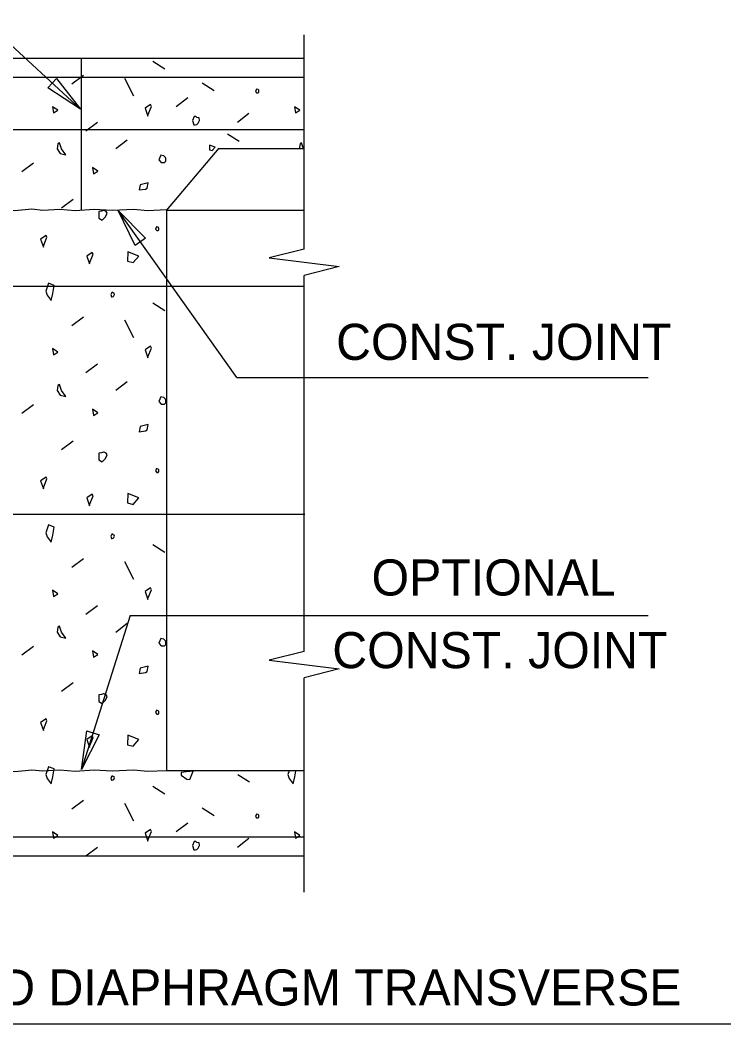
# Model space of a CAD drawing. Extents: x 0 to 34, y 0 to 23.5.
# Drawn here: x 21.208 to 24.17, y 15.614 to 19.798 of the extents above; entities that cross this region are included whole.
import ezdxf

# ---------------------------------------------------------------- set-up
doc = ezdxf.new("R2010")
doc.units = 0
for name, color, linetype in [('BRDG_ANNO_General-Notes', 7, 'Continuous'), ('BRDG_BASE_Obj-Line', 7, 'Continuous'), ('BRDG_BASE_Pattern', 7, 'Continuous'), ('BRDG_BASE_Rebar', 7, 'Continuous')]:
    doc.layers.add(name, color=color, linetype=linetype)

msp = doc.modelspace()

# ---------------------------------------------------------------- linework, layer by layer
at = {"layer": 'BRDG_ANNO_General-Notes'}
for p, q in [((20.8763, 19.966), (21.4595, 19.4264)), ((21.324, 19.5155), (21.3602, 19.5546)), ((21.3602, 19.5546), (21.4595, 19.4264)), ((21.4595, 19.4264), (21.324, 19.5155)), ((22.1111, 18.3085), (21.6165, 19.0045)), ((21.6874, 18.8586), (21.6165, 19.0045)), ((21.6165, 19.0045), (21.7309, 18.8896)), ((21.7309, 18.8896), (21.6874, 18.8586)), ((22.1111, 18.3085), (23.8259, 18.3085)), ((21.6666, 17.3169), (21.4636, 16.6744)), ((21.6666, 17.3169), (23.8259, 17.3169)), ((21.4636, 16.6744), (21.4864, 16.835)), ((21.4864, 16.835), (21.5372, 16.8189)), ((21.5372, 16.8189), (21.4636, 16.6744)), ((20.1671, 15.6141), (24.1701, 15.6141))]:
    msp.add_line(p, q, dxfattribs=at)
at = {"layer": 'BRDG_BASE_Obj-Line'}
for p, q in [((22.3924, 18.8436), (22.3924, 19.7368)), ((22.3924, 19.6379), (18.0383, 19.6379)), ((21.4622, 19.6379), (21.4622, 19.0045)), ((21.8185, 19.0045), (22.0383, 19.2644)), ((22.3924, 19.2618), (22.0362, 19.2618)), ((22.3924, 19.0045), (21.8185, 19.0045)), ((21.8185, 19.0045), (21.8185, 16.6691)), ((22.3924, 18.8436), (22.2466, 18.8071)), ((22.2466, 18.8071), (22.5383, 18.7707)), ((22.5383, 18.7707), (22.3924, 18.7342)), ((22.3924, 17.1665), (22.3924, 18.7342)), ((22.3924, 17.1665), (22.2466, 17.1301)), ((22.2466, 17.1301), (22.5383, 17.0936)), ((22.5383, 17.0936), (22.3924, 17.0571)), ((22.3924, 16.1639), (22.3924, 17.0571)), ((22.3924, 16.6691), (21.8185, 16.6691)), ((22.3924, 16.3129), (18.0383, 16.3129))]:
    msp.add_line(p, q, dxfattribs=at)
for points in [[(21.8185, 19.0067), (21.7392, 19.0034), (21.6823, 19.0088), (21.5921, 19.0046), (21.5175, 19.0091), (21.4371, 19.0036), (21.3743, 19.0093), (21.3036, 19.0046), (21.2566, 19.01), (21.1859, 19.0029), (21.1369, 19.0093), (21.106, 19.0067)], [(21.8185, 16.6691), (21.7392, 16.6658), (21.6823, 16.6713), (21.5921, 16.6671), (21.5175, 16.6715), (21.4371, 16.6661), (21.3743, 16.6717), (21.3036, 16.6671), (21.2566, 16.6724), (21.1859, 16.6654), (21.1369, 16.6717), (21.106, 16.6691)]]:
    msp.add_lwpolyline(points, dxfattribs=at)
at = {"layer": 'BRDG_BASE_Pattern'}
for p, q in [((21.7613, 19.6269), (21.8107, 19.5956)), ((21.4722, 19.5672), (21.4241, 19.5306)), ((21.6438, 19.5561), (21.6804, 19.4826)), ((21.9676, 19.5366), (22.0171, 19.5053)), ((21.9071, 19.4734), (21.859, 19.4368)), ((22.1618, 19.4084), (22.1136, 19.3718)), ((21.5305, 19.3715), (21.4824, 19.3349)), ((21.6548, 19.2976), (21.6067, 19.2609)), ((22.0718, 19.3245), (22.1213, 19.2932)), ((21.2637, 19.202), (21.2156, 19.1654)), ((21.4288, 19.0508), (21.3806, 19.0142)), ((21.8355, 19.0312), (21.8391, 19.0289)), ((21.7613, 18.6195), (21.8107, 18.5883)), ((21.4722, 18.5598), (21.4241, 18.5232)), ((21.6438, 18.5487), (21.6804, 18.4752)), ((21.5305, 18.3642), (21.4824, 18.3276)), ((21.6548, 18.2902), (21.6067, 18.2536)), ((21.2637, 18.1946), (21.2156, 18.158)), ((21.4288, 18.0435), (21.3806, 18.0069)), ((21.7613, 17.6122), (21.8107, 17.5809)), ((21.4722, 17.5525), (21.4241, 17.5159)), ((21.6438, 17.5414), (21.6804, 17.4679)), ((21.5305, 17.3568), (21.4824, 17.3202)), ((21.6548, 17.2829), (21.6067, 17.2462)), ((21.2637, 17.1873), (21.2156, 17.1507)), ((21.4288, 17.0361), (21.3806, 16.9995)), ((22.1149, 16.6539), (22.1644, 16.6226)), ((21.7613, 16.6048), (21.8107, 16.5736)), ((21.4722, 16.5452), (21.4241, 16.5085)), ((21.6438, 16.5341), (21.6804, 16.4605)), ((21.9676, 16.5145), (22.0171, 16.4833)), ((21.9071, 16.4514), (21.859, 16.4148)), ((22.1618, 16.3864), (22.1136, 16.3498)), ((21.5305, 16.3495), (21.4824, 16.3129))]:
    msp.add_line(p, q, dxfattribs=at)
for points in [[(22.1932, 19.5105), (22.1886, 19.5003), (22.194, 19.4947), (22.2006, 19.4947), (22.2033, 19.4977), (22.2033, 19.5031), (22.2024, 19.5057), (22.1996, 19.5087)], [(21.3438, 19.4367), (21.3474, 19.4109), (21.3659, 19.422)], [(21.7298, 19.4313), (21.7412, 19.3981), (21.7412, 19.4017), (21.7559, 19.4386), (21.7521, 19.446)], [(22.3521, 19.4367), (22.3558, 19.4109), (22.3743, 19.422)], [(21.9264, 19.3796), (21.9322, 19.3611), (21.9376, 19.3611), (21.9451, 19.363), (21.9505, 19.3683), (21.9558, 19.3796), (21.9543, 19.3905), (21.9451, 19.3924), (21.9411, 19.3962), (21.9338, 19.3962)], [(21.3662, 19.2826), (21.3621, 19.2619), (21.3759, 19.2416), (21.3989, 19.237), (21.3805, 19.2614), (21.3727, 19.2867)], [(21.9981, 19.2771), (21.9972, 19.2573), (22.0092, 19.2546), (22.0207, 19.2679)], [(21.7952, 19.2355), (21.7859, 19.2153), (21.7967, 19.2041), (21.8099, 19.2041), (21.8154, 19.2099), (21.8154, 19.2207), (21.8135, 19.226), (21.8078, 19.232)], [(21.5104, 19.1836), (21.5141, 19.1578), (21.5326, 19.1689)], [(21.7082, 19.1119), (21.7045, 19.0899), (21.7303, 19.0936), (21.7376, 19.0972), (21.7413, 19.1193)], [(21.5369, 19.0005), (21.5369, 18.9726), (21.5496, 18.9636), (21.5534, 18.9672), (21.5643, 18.9783), (21.5717, 18.9931), (21.5663, 19.0005), (21.5589, 19.0041), (21.5553, 19.0041), (21.5481, 19.002)], [(21.7767, 18.9361), (21.7721, 18.926), (21.7775, 18.9204), (21.7841, 18.9204), (21.7868, 18.9233), (21.7868, 18.9288), (21.7859, 18.9314), (21.7831, 18.9344)], [(21.294, 18.8854), (21.3054, 18.8521), (21.3054, 18.8557), (21.3202, 18.8927), (21.3164, 18.9001)], [(21.4862, 18.8146), (21.4976, 18.7815), (21.4976, 18.785), (21.5123, 18.822), (21.5085, 18.8294)], [(21.6575, 18.8322), (21.6557, 18.7927), (21.6796, 18.7871), (21.7027, 18.8138)], [(21.3264, 18.701), (21.3152, 18.6679), (21.3208, 18.6513), (21.3374, 18.6292), (21.3447, 18.6586), (21.3503, 18.6918)], [(21.5868, 18.6537), (21.5897, 18.6445), (21.5923, 18.6445), (21.5961, 18.6455), (21.5988, 18.6481), (21.6015, 18.6537), (21.6007, 18.6593), (21.5961, 18.6602), (21.5941, 18.6621), (21.5905, 18.6621)], [(21.3438, 18.4294), (21.3474, 18.4035), (21.3659, 18.4146)], [(21.7298, 18.424), (21.7412, 18.3907), (21.7412, 18.3943), (21.7559, 18.4313), (21.7521, 18.4386)], [(21.3662, 18.2753), (21.3621, 18.2545), (21.3759, 18.2342), (21.3989, 18.2297), (21.3805, 18.2541), (21.3727, 18.2794)], [(21.7952, 18.2282), (21.7859, 18.208), (21.7967, 18.1967), (21.8099, 18.1967), (21.8154, 18.2026), (21.8154, 18.2134), (21.8135, 18.2187), (21.8078, 18.2246)], [(21.5104, 18.1762), (21.5141, 18.1504), (21.5326, 18.1615)], [(21.7082, 18.1046), (21.7045, 18.0826), (21.7303, 18.0862), (21.7376, 18.0898), (21.7413, 18.112)], [(21.5369, 17.9932), (21.5369, 17.9653), (21.5496, 17.9563), (21.5534, 17.9599), (21.5643, 17.971), (21.5717, 17.9858), (21.5663, 17.9932), (21.5589, 17.9967), (21.5553, 17.9967), (21.5481, 17.9947)], [(21.7767, 17.9288), (21.7721, 17.9187), (21.7775, 17.9131), (21.7841, 17.9131), (21.7868, 17.916), (21.7868, 17.9214), (21.7859, 17.9241), (21.7831, 17.927)], [(21.294, 17.878), (21.3054, 17.8448), (21.3054, 17.8483), (21.3202, 17.8854), (21.3164, 17.8927)], [(21.6575, 17.8249), (21.6557, 17.7853), (21.6796, 17.7797), (21.7027, 17.8065)], [(21.4862, 17.8073), (21.4976, 17.7741), (21.4976, 17.7777), (21.5123, 17.8147), (21.5085, 17.822)], [(21.3264, 17.6936), (21.3152, 17.6605), (21.3208, 17.644), (21.3374, 17.6218), (21.3447, 17.6513), (21.3503, 17.6845)], [(21.5868, 17.6464), (21.5897, 17.6372), (21.5923, 17.6372), (21.5961, 17.6381), (21.5988, 17.6408), (21.6015, 17.6464), (21.6007, 17.6519), (21.5961, 17.6529), (21.5941, 17.6548), (21.5905, 17.6548)], [(21.3438, 17.422), (21.3474, 17.3962), (21.3659, 17.4073)], [(21.7298, 17.4166), (21.7412, 17.3834), (21.7412, 17.387), (21.7559, 17.424), (21.7521, 17.4313)], [(21.3662, 17.2679), (21.3621, 17.2472), (21.3759, 17.2269), (21.3989, 17.2223), (21.3805, 17.2467), (21.3727, 17.272)], [(21.7952, 17.2208), (21.7859, 17.2006), (21.7967, 17.1894), (21.8099, 17.1894), (21.8154, 17.1953), (21.8154, 17.206), (21.8135, 17.2114), (21.8078, 17.2173)], [(21.5104, 17.1689), (21.5141, 17.1431), (21.5326, 17.1542)], [(21.7082, 17.0972), (21.7045, 17.0752), (21.7303, 17.0789), (21.7376, 17.0825), (21.7413, 17.1046)], [(21.5369, 16.9858), (21.5369, 16.9579), (21.5496, 16.949), (21.5534, 16.9526), (21.5643, 16.9636), (21.5717, 16.9784), (21.5663, 16.9858), (21.5589, 16.9894), (21.5553, 16.9894), (21.5481, 16.9873)], [(21.7767, 16.9215), (21.7721, 16.9114), (21.7775, 16.9057), (21.7841, 16.9057), (21.7868, 16.9086), (21.7868, 16.9141), (21.7859, 16.9167), (21.7831, 16.9197)], [(21.294, 16.8707), (21.3054, 16.8374), (21.3054, 16.841), (21.3202, 16.878), (21.3164, 16.8854)], [(21.4862, 16.7999), (21.4976, 16.7668), (21.4976, 16.7703), (21.5123, 16.8073), (21.5085, 16.8147)], [(21.6575, 16.8176), (21.6557, 16.778), (21.6796, 16.7724), (21.7027, 16.7991)], [(21.3264, 16.6863), (21.3152, 16.6532), (21.3208, 16.6366), (21.3374, 16.6145), (21.3447, 16.644), (21.3503, 16.6771)], [(21.901, 16.6644), (21.8789, 16.6625), (21.8789, 16.6515), (21.9029, 16.6349), (21.9158, 16.6331), (21.9288, 16.668)], [(21.5868, 16.6391), (21.5897, 16.6298), (21.5923, 16.6298), (21.5961, 16.6308), (21.5988, 16.6334), (21.6015, 16.6391), (21.6007, 16.6446), (21.5961, 16.6455), (21.5941, 16.6474), (21.5905, 16.6474)], [(22.1932, 16.4884), (22.1886, 16.4783), (22.194, 16.4727), (22.2006, 16.4727), (22.2033, 16.4756), (22.2033, 16.481), (22.2024, 16.4837), (22.1996, 16.4867)], [(21.3438, 16.4147), (21.3474, 16.3889), (21.3659, 16.3999)], [(21.7298, 16.4093), (21.7412, 16.376), (21.7412, 16.3796), (21.7559, 16.4166), (21.7521, 16.424)], [(22.3521, 16.4147), (22.3558, 16.3889), (22.3743, 16.3999)], [(21.9264, 16.3576), (21.9322, 16.3391), (21.9376, 16.3391), (21.9451, 16.3409), (21.9505, 16.3463), (21.9558, 16.3576), (21.9543, 16.3685), (21.9451, 16.3704), (21.9411, 16.3742), (21.9338, 16.3742)]]:
    msp.add_lwpolyline(points, close=True, dxfattribs=at)
for points in [[(22.3746, 19.2826), (22.3705, 19.262)], [(22.3887, 19.2619), (22.381, 19.2867), (22.3746, 19.2826)], [(22.3289, 16.6691), (22.3235, 16.6532), (22.3292, 16.6366), (22.3458, 16.6145), (22.3531, 16.644), (22.3573, 16.6691)]]:
    msp.add_lwpolyline(points, dxfattribs=at)
at = {"layer": 'BRDG_BASE_Rebar'}
for p, q in [((22.3924, 19.5587), (18.0383, 19.5587)), ((22.3924, 19.341), (18.0383, 19.341)), ((22.3924, 18.6879), (18.0383, 18.6879)), ((22.3944, 17.7379), (18.0383, 17.7379)), ((22.3924, 16.392), (18.0383, 16.392))]:
    msp.add_line(p, q, dxfattribs=at)

# ---------------------------------------------------------------- texts
at = {"layer": 'BRDG_ANNO_General-Notes'}
for s, height, p in [('CONST. JOINT', 0.150417, (22.5251, 18.3818)), ('OPTIONAL', 0.15042, (22.6727, 17.3997)), ('CONST. JOINT', 0.150417, (22.5092, 17.0968)), ('SLAB AND DIAPHRAGM TRANSVERSE', 0.150417, (20.2759, 15.6909))]:
    msp.add_text(s, height=height, dxfattribs=at).set_placement(p)

doc.saveas('drawing.dxf')
